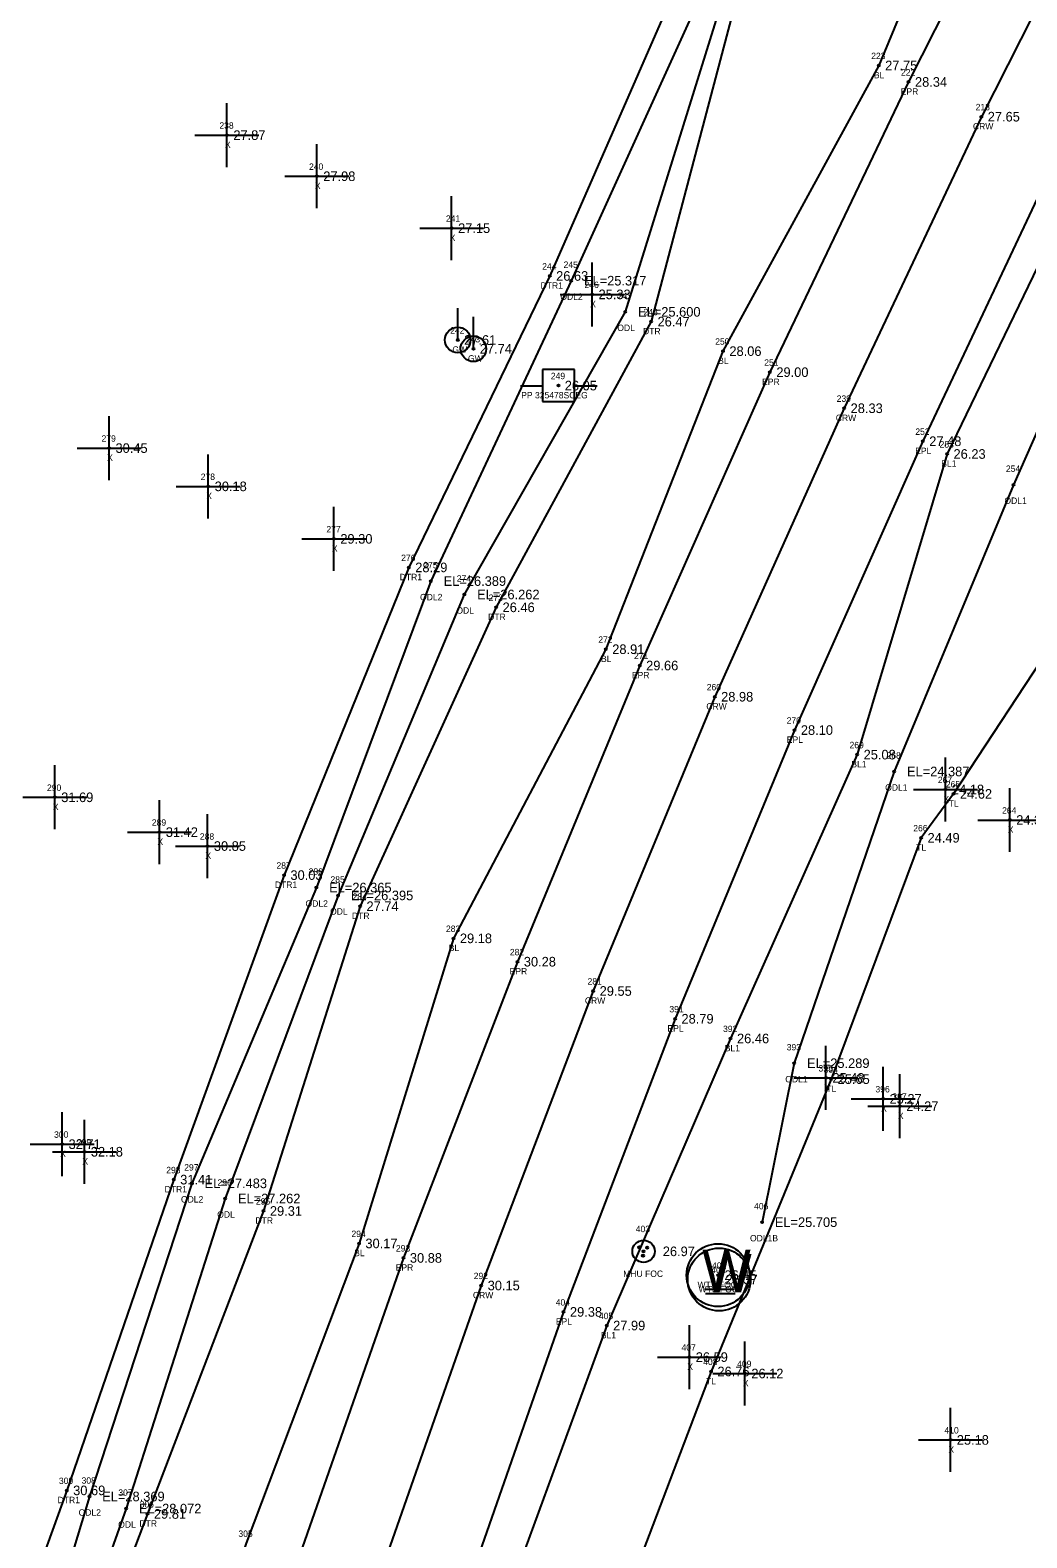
# Model space of a CAD drawing. Extents: x 2042211 to 2045853, y 303080 to 309569.
# Drawn here: x 2042888.3 to 2043044.1, y 307971.4 to 308207.1 of the extents above; entities that cross this region are included whole.
import ezdxf

# ---------------------------------------------------------------- set-up
doc = ezdxf.new("R2010")
doc.units = 0
for name, color, linetype in [('BR_500YR_SCOUR', 7, 'Continuous'), ('RD_DTM_BkLn1', 7, 'Continuous'), ('RD_DTM_BkLn_txCode', 7, 'Continuous'), ('RD_EX_H2O', 7, 'Continuous'), ('RD_EX_H2O_txCode', 7, 'Continuous'), ('RD_EX_Misc', 7, 'Continuous'), ('RD_EX_Misc_txCode', 7, 'Continuous'), ('RD_EX_Road', 7, 'Continuous'), ('RD_EX_Road_txCode', 7, 'Continuous'), ('RD_EX_TX_H2O_ELEV', 7, 'Continuous'), ('RD_EX_TX_Misc_ELEV', 7, 'Continuous'), ('RD_EX_TX_Road_ELEV', 7, 'Continuous'), ('RD_EX_TX_UT_ELEV', 7, 'Continuous'), ('RD_EX_TX_VEG_ELEV', 7, 'Continuous'), ('RD_EX_UT_txCode', 7, 'Continuous'), ('RD_EX_VEG_txCode', 7, 'Continuous'), ('RD_HC_Survey_ELEV', 7, 'Continuous'), ('RD_HC_Survey_txCode', 7, 'Continuous'), ('RD_SMD_Locator', 7, 'Continuous')]:
    doc.layers.add(name, color=color, linetype=linetype)

msp = doc.modelspace()

# ---------------------------------------------------------------- linework, layer by layer
at = {"layer": 'BR_500YR_SCOUR'}
for p, q in [((2042955.12, 308158.64), (2042955.12, 308163.64)), ((2042957.57, 308157.26), (2042957.57, 308162.26)), ((2042973.35, 308154.01), (2042968.35, 308154.01)), ((2042968.35, 308154.01), (2042968.35, 308149.01)), ((2042973.35, 308149.01), (2042973.35, 308154.01)), ((2042964.91, 308151.45), (2042968.38, 308151.45)), ((2042973.27, 308151.45), (2042976.91, 308151.45)), ((2042968.35, 308149.01), (2042973.35, 308149.01)), ((2042993.68, 308010.24), (2042998.31, 308010.24)), ((2042993.84, 308009.56), (2042998.47, 308009.56))]:
    msp.add_line(p, q, dxfattribs=at)
msp.add_lwpolyline([(2043048.7, 308112.2), (2043032.62, 308087.68), (2043027.55, 308080.82), (2043013.5, 308043.09), (2042994.71, 307997.39), (2042983.47, 307967.75), (2042952.97, 307870.73), (2042935.66, 307809.47), (2042918.92, 307737.74), (2042902.79, 307636.4), (2042902.54, 307635.29), (2042891, 307519.21), (2042885.61, 307482.85), (2042881.1, 307379.92), (2042880.44, 307351.7), (2042880.19, 307284.9)], dxfattribs=at)
for centre, radius in [((2042955.12, 308158.64), 2), ((2042955.12, 308158.64), 0.15), ((2042957.57, 308157.26), 2), ((2042957.57, 308157.26), 0.15), ((2042970.85, 308151.51), 0.15), ((2043032.62, 308087.68), 0.15), ((2043027.55, 308080.82), 0.15), ((2043013.5, 308043.09), 0.15), ((2042984.17, 308016.17), 1.75), ((2042983.51, 308016.8), 0.175), ((2042984.17, 308016.17), 0.15), ((2042984.73, 308016.73), 0.175), ((2042995.81, 308012.45), 4.91), ((2042995.97, 308011.76), 4.91), ((2042984.08, 308015.51), 0.175), ((2042995.81, 308012.45), 0.15), ((2042995.97, 308011.76), 0.15), ((2042994.71, 307997.39), 0.15)]:
    msp.add_circle(centre, radius, dxfattribs=at)
at = {"layer": 'RD_DTM_BkLn1'}
for points in [[(2043146.35, 308418.61), (2043116.28, 308377.51), (2043090.22, 308335.44), (2043066.45, 308290.88), (2043040.21, 308248.13), (2043020.93, 308201.56), (2042996.58, 308156.9), (2042978.27, 308110.3), (2042954.46, 308065.1), (2042939.69, 308017.41), (2042922.06, 307970.53), (2042906.59, 307922.57), (2042893.03, 307873.93), (2042879.97, 307825.46), (2042869.74, 307776.07), (2042859.54, 307726.73)], [(2043161.13, 308408.97), (2043133.81, 308366.92), (2043082.92, 308281.6), (2043059.61, 308238.25), (2043036.96, 308193.55), (2043015.53, 308147.97), (2042995.29, 308102.87), (2042976.3, 308056.87), (2042958.8, 308010.83), (2042942.32, 307963.75), (2042927.06, 307916.53), (2042912.57, 307868.35), (2042899.47, 307820.61), (2042887.68, 307772.41), (2042877.12, 307722.98), (2042868.22, 307675.1), (2042860.12, 307626.05), (2042853.34, 307576.87), (2042847.77, 307527.39), (2042843.87, 307477.74), (2042841.31, 307428.69), (2042840.04, 307379.1), (2042839.81, 307329.37), (2042840.93, 307280.46)], [(2043084.04, 308249.78), (2043074.97, 308230.46), (2043053.22, 308185.62), (2043031.61, 308140.82), (2043017.56, 308093.82), (2042997.77, 308049.45), (2042978.41, 308004.57), (2042961.32, 307957.89), (2042945.16, 307911.22), (2042932.79, 307863.05), (2042919.73, 307815.78), (2042908.87, 307767.34), (2042898.28, 307719.5), (2042889.52, 307671.44), (2042882.14, 307623.35), (2042877.76, 307594.41)]]:
    msp.add_lwpolyline(points, dxfattribs=at)
at = {"layer": 'RD_EX_H2O'}
for points in [[(2043129.27, 308428.82), (2043103.11, 308386.53), (2043087.59, 308358.52), (2043078.21, 308342.14), (2043052.09, 308299.16), (2043025.98, 308255.36), (2043015.05, 308240.46), (2043007.57, 308236.11), (2042996.98, 308213.48), (2042981.31, 308163.04), (2042956.15, 308118.86), (2042936.41, 308071.81), (2042918.77, 308024.43), (2042903.29, 307975.96), (2042886.4, 307928.42), (2042872.04, 307879.53), (2042857.18, 307831.23), (2042843.33, 307782.22), (2042831.48, 307730.99), (2042823.97, 307682.68), (2042817.59, 307631.17), (2042809.6, 307580.86), (2042807.78, 307554.78)], [(2043043.85, 308319.04), (2043032.27, 308309.6), (2043013.89, 308261.63), (2043005.61, 308245.64), (2043001.64, 308238.83), (2042990.42, 308216.49), (2042969.5, 308168.65), (2042947.48, 308123.09), (2042927.97, 308074.99), (2042910.74, 308027.38), (2042894.01, 307978.8), (2042876.75, 307931.05), (2042864.86, 307881.34), (2042850.03, 307832.86), (2042838.55, 307782.98)], [(2043049.1, 308319.34), (2043039.24, 308307.44), (2043016.82, 308260.67), (2043010.35, 308243.14), (2043005.62, 308237.14), (2042994.18, 308214.82), (2042972.85, 308167.91), (2042950.92, 308120.95), (2042933.02, 308073.04), (2042913.55, 308026.8), (2042897.55, 307977.85), (2042882.86, 307929.46), (2042868.15, 307880.57), (2042854.72, 307831.84), (2042841.01, 307782.54)], [(2043009.25, 308234.96), (2042998.85, 308212.71), (2042985.35, 308161.51), (2042961.13, 308116.85), (2042939.86, 308070.12), (2042924.76, 308022.48), (2042906.64, 307975.12), (2042888.69, 307927.84), (2042874.66, 307878.9), (2042861.89, 307830.47), (2042846.22, 307781.58)], [(2043061.8, 308180.79), (2043041.98, 308136.02), (2043023.34, 308091.19), (2043007.72, 308045.58), (2043002.68, 308020.73)]]:
    msp.add_lwpolyline(points, dxfattribs=at)
at = {"layer": 'RD_EX_Misc'}
for p, q in [((2042919.05, 308185.67), (2042919.05, 308195.67)), ((2042914.05, 308190.67), (2042924.05, 308190.67)), ((2042933.1, 308179.24), (2042933.1, 308189.24)), ((2042928.1, 308184.24), (2042938.1, 308184.24)), ((2042954.17, 308171.12), (2042954.17, 308181.12)), ((2042949.17, 308176.12), (2042959.17, 308176.12)), ((2042976.13, 308160.77), (2042976.13, 308170.77)), ((2042971.13, 308165.77), (2042981.13, 308165.77)), ((2042900.63, 308136.74), (2042900.63, 308146.74)), ((2042895.63, 308141.74), (2042905.63, 308141.74)), ((2042916.13, 308130.76), (2042916.13, 308140.76)), ((2042911.13, 308135.76), (2042921.13, 308135.76)), ((2042935.77, 308122.55), (2042935.77, 308132.55)), ((2042930.77, 308127.55), (2042940.77, 308127.55)), ((2042892.14, 308082.15), (2042892.14, 308092.15)), ((2043031.37, 308083.37), (2043031.37, 308093.37)), ((2042887.14, 308087.15), (2042897.14, 308087.15)), ((2043026.37, 308088.37), (2043036.37, 308088.37)), ((2043041.41, 308078.6), (2043041.41, 308088.6)), ((2042908.49, 308076.71), (2042908.49, 308086.71)), ((2042916, 308074.53), (2042916, 308084.53)), ((2043036.41, 308083.6), (2043046.41, 308083.6)), ((2042903.49, 308081.71), (2042913.49, 308081.71)), ((2042911, 308079.53), (2042921, 308079.53)), ((2043012.68, 308038.28), (2043012.68, 308048.28)), ((2043021.61, 308035.01), (2043021.61, 308045.01)), ((2043007.68, 308043.28), (2043017.68, 308043.28)), ((2043024.23, 308033.86), (2043024.23, 308043.86)), ((2043016.61, 308040.01), (2043026.61, 308040.01)), ((2042893.29, 308027.92), (2042893.29, 308037.92)), ((2043019.23, 308038.86), (2043029.23, 308038.86)), ((2042896.77, 308026.74), (2042896.77, 308036.74)), ((2042888.29, 308032.92), (2042898.29, 308032.92)), ((2042891.77, 308031.74), (2042901.77, 308031.74)), ((2042991.32, 307994.64), (2042991.32, 308004.64)), ((2043000.01, 307992.07), (2043000.01, 308002.07)), ((2042986.32, 307999.64), (2042996.32, 307999.64)), ((2042995.01, 307997.07), (2043005.01, 307997.07)), ((2043032.12, 307981.69), (2043032.12, 307991.69)), ((2043027.12, 307986.69), (2043037.12, 307986.69))]:
    msp.add_line(p, q, dxfattribs=at)
at = {"layer": 'RD_EX_Road'}
for points in [[(2043150.45, 308415.87), (2043123.31, 308373.62), (2043097.1, 308331.18), (2043072.09, 308287.75), (2043048.26, 308243.82), (2043025.59, 308198.98), (2043003.92, 308153.61), (2042983.57, 308107.75), (2042964.45, 308061.45), (2042946.64, 308015.14), (2042930.05, 307967.71), (2042914.65, 307920.21), (2042900.21, 307872.25), (2042887.2, 307823.91), (2042875.38, 307775.02), (2042864.88, 307726.03)], [(2043172.79, 308402.16), (2043145.1, 308359.37), (2043119.63, 308317.71), (2043094.79, 308274.94), (2043071.92, 308232.51), (2043049.11, 308188.03), (2043027.82, 308142.81), (2043007.75, 308097.66), (2042989.09, 308052.53), (2042971.66, 308006.7), (2042955.42, 307960.12), (2042939.67, 307912.41), (2042925.65, 307865.09), (2042912.69, 307817.39), (2042901.29, 307769.38)]]:
    msp.add_lwpolyline(points, dxfattribs=at)
at = {"layer": 'RD_SMD_Locator'}
for centre in [(2043020.93, 308201.56), (2043025.59, 308198.98), (2043036.96, 308193.55), (2042919.05, 308190.67), (2042933.1, 308184.24), (2042954.17, 308176.12), (2042969.5, 308168.65), (2042972.85, 308167.91), (2042976.13, 308165.77), (2042981.31, 308163.04), (2042985.35, 308161.51), (2042996.58, 308156.9), (2043003.92, 308153.61), (2043015.53, 308147.97), (2042900.63, 308141.74), (2043027.82, 308142.81), (2043031.61, 308140.82), (2042916.13, 308135.76), (2043041.98, 308136.02), (2042935.77, 308127.55), (2042947.48, 308123.09), (2042950.92, 308120.95), (2042956.15, 308118.86), (2042961.13, 308116.85), (2042978.27, 308110.3), (2042983.57, 308107.75), (2042995.29, 308102.87), (2043007.75, 308097.66), (2043017.56, 308093.82), (2043023.34, 308091.19), (2042892.14, 308087.15), (2043031.37, 308088.37), (2043041.41, 308083.6), (2042908.49, 308081.71), (2042916, 308079.53), (2042927.97, 308074.99), (2042933.02, 308073.04), (2042936.41, 308071.81), (2042939.86, 308070.12), (2042954.46, 308065.1), (2042964.45, 308061.45), (2042976.3, 308056.87), (2042989.09, 308052.53), (2042997.77, 308049.45), (2043007.72, 308045.58), (2043012.68, 308043.28), (2043021.61, 308040.01), (2043024.23, 308038.86), (2042893.29, 308032.92), (2042896.77, 308031.74), (2042910.74, 308027.38), (2042913.55, 308026.8), (2042918.77, 308024.43), (2042924.76, 308022.48), (2043002.68, 308020.73), (2042939.69, 308017.41), (2042946.64, 308015.14), (2042958.8, 308010.83), (2042971.66, 308006.7), (2042978.41, 308004.57), (2042991.32, 307999.64), (2043000.01, 307997.07), (2043032.12, 307986.69), (2042894.01, 307978.8), (2042897.55, 307977.85), (2042903.29, 307975.96), (2042906.64, 307975.12)]:
    msp.add_circle(centre, 0.15, dxfattribs=at)

# ---------------------------------------------------------------- texts
at = {"layer": 'BR_500YR_SCOUR'}
for p in [(2042993.35, 308010.45), (2042993.5, 308009.76)]:
    msp.add_text('W', height=6, dxfattribs=at).set_placement(p)
at = {"layer": 'RD_DTM_BkLn_txCode'}
for s, p in [('223', (2043019.75, 308202.56)), ('BL', (2043020.17, 308199.56)), ('250', (2042995.36, 308157.9)), ('BL', (2042995.83, 308154.9)), ('253', (2043030.43, 308141.82)), ('BL1', (2043030.69, 308138.82)), ('272', (2042977.09, 308111.3)), ('BL', (2042977.51, 308108.3)), ('269', (2043016.36, 308094.82)), ('BL1', (2043016.64, 308091.82)), ('283', (2042953.28, 308066.1)), ('BL', (2042953.71, 308063.1)), ('392', (2042996.59, 308050.45)), ('BL1', (2042996.85, 308047.45)), ('294', (2042938.51, 308018.41)), ('BL', (2042938.93, 308015.41)), ('405', (2042977.19, 308005.57)), ('BL1', (2042977.49, 308002.57)), ('305', (2042920.84, 307971.53))]:
    msp.add_text(s, height=1, dxfattribs=at).set_placement(p)
at = {"layer": 'RD_EX_H2O_txCode'}
for s, p in [('244', (2042968.32, 308169.65)), ('245', (2042971.67, 308169.91)), ('DTR1', (2042968.07, 308166.65)), ('ODL2', (2042971.16, 308164.91)), ('247', (2042980.13, 308165.04)), ('248', (2042984.16, 308162.51)), ('ODL', (2042980.06, 308160.04)), ('DTR', (2042984.08, 308159.51)), ('254', (2043040.8, 308138.02)), ('ODL1', (2043040.57, 308133.02)), ('276', (2042946.28, 308124.09)), ('275', (2042949.74, 308122.95)), ('DTR1', (2042946.05, 308121.09)), ('274', (2042954.97, 308120.86)), ('ODL2', (2042949.23, 308117.95)), ('273', (2042959.95, 308117.85)), ('ODL', (2042954.91, 308115.86)), ('DTR', (2042959.87, 308114.85)), ('268', (2043022.14, 308093.19)), ('ODL1', (2043021.93, 308088.19)), ('287', (2042926.79, 308075.99)), ('286', (2042931.82, 308075.04)), ('DTR1', (2042926.54, 308072.99)), ('285', (2042935.23, 308073.81)), ('ODL2', (2042931.33, 308070.04)), ('284', (2042938.68, 308071.12)), ('ODL', (2042935.17, 308068.81)), ('DTR', (2042938.59, 308068.12)), ('393', (2043006.54, 308047.58)), ('ODL1', (2043006.31, 308042.58)), ('298', (2042909.56, 308028.38)), ('297', (2042912.37, 308028.8)), ('DTR1', (2042909.31, 308025.38)), ('296', (2042917.57, 308026.43)), ('ODL2', (2042911.86, 308023.8)), ('295', (2042923.58, 308023.48)), ('406', (2043001.44, 308022.73)), ('ODL', (2042917.53, 308021.43)), ('DTR', (2042923.5, 308020.48)), ('ODL1B', (2043000.8, 308017.73)), ('308', (2042896.33, 307979.85)), ('309', (2042892.79, 307979.8)), ('307', (2042902.07, 307977.96)), ('DTR1', (2042892.58, 307976.8)), ('306', (2042905.4, 307976.12)), ('ODL2', (2042895.86, 307974.85)), ('ODL', (2042902.05, 307972.96)), ('DTR', (2042905.37, 307973.12))]:
    msp.add_text(s, height=1, dxfattribs=at).set_placement(p)
at = {"layer": 'RD_EX_Misc_txCode'}
for s, p in [('238', (2042917.87, 308191.67)), ('X', (2042918.74, 308188.67)), ('240', (2042931.88, 308185.24)), ('X', (2042932.79, 308182.24)), ('241', (2042953.27, 308177.12)), ('X', (2042953.86, 308174.12)), ('246', (2042974.93, 308166.77)), ('X', (2042975.82, 308163.77)), ('279', (2042899.45, 308142.74)), ('X', (2042900.32, 308139.74)), ('278', (2042914.95, 308136.76)), ('X', (2042915.81, 308133.76)), ('277', (2042934.59, 308128.55)), ('X', (2042935.45, 308125.55)), ('267', (2043030.16, 308089.37)), ('290', (2042890.92, 308088.15)), ('X', (2043031.05, 308086.37)), ('X', (2042891.83, 308085.15)), ('264', (2043040.2, 308084.6)), ('289', (2042907.31, 308082.71)), ('X', (2043041.09, 308081.6)), ('X', (2042908.18, 308079.71)), ('288', (2042914.82, 308080.53)), ('X', (2042915.68, 308077.53)), ('395', (2043011.5, 308044.28)), ('X', (2043012.37, 308041.28)), ('396', (2043020.41, 308041.01)), ('397', (2043023.05, 308039.86)), ('X', (2043021.29, 308038.01)), ('X', (2043023.92, 308036.86)), ('300', (2042892.03, 308033.92)), ('299', (2042895.59, 308032.74)), ('X', (2042892.98, 308030.92)), ('X', (2042896.45, 308029.74)), ('407', (2042990.1, 308000.64)), ('X', (2042991, 307997.64)), ('409', (2042998.79, 307998.07)), ('X', (2042999.69, 307995.07)), ('410', (2043031.19, 307987.69)), ('X', (2043031.81, 307984.69))]:
    msp.add_text(s, height=1, dxfattribs=at).set_placement(p)
at = {"layer": 'RD_EX_Road_txCode'}
for s, p in [('222', (2043024.41, 308199.98)), ('EPR', (2043024.36, 308196.98)), ('251', (2043003.02, 308154.61)), ('EPR', (2043002.69, 308151.61)), ('252', (2043026.64, 308143.81)), ('EPL', (2043026.62, 308140.81)), ('271', (2042982.67, 308108.75)), ('EPR', (2042982.34, 308105.75)), ('270', (2043006.53, 308098.66)), ('EPL', (2043006.55, 308095.66)), ('282', (2042963.27, 308062.45)), ('EPR', (2042963.23, 308059.45)), ('391', (2042988.2, 308053.53)), ('EPL', (2042987.89, 308050.53)), ('293', (2042945.46, 308016.14)), ('EPR', (2042945.42, 308013.14)), ('404', (2042970.44, 308007.7)), ('EPL', (2042970.45, 308004.7))]:
    msp.add_text(s, height=1, dxfattribs=at).set_placement(p)
at = {"layer": 'RD_EX_TX_H2O_ELEV'}
for s, p in [('26.63', (2042970.5, 308167.9)), ('EL=25.317', (2042974.85, 308167.16)), ('EL=25.600', (2042983.31, 308162.29)), ('26.47', (2042986.35, 308160.76)), ('28.29', (2042948.48, 308122.34)), ('EL=26.389', (2042952.92, 308120.2)), ('EL=26.262', (2042958.15, 308118.11)), ('26.46', (2042962.13, 308116.1)), ('EL=24.387', (2043025.34, 308090.44)), ('30.03', (2042928.97, 308074.24)), ('EL=26.365', (2042935.02, 308072.29)), ('EL=26.395', (2042938.41, 308071.06)), ('27.74', (2042940.86, 308069.37)), ('EL=25.289', (2043009.72, 308044.83)), ('31.41', (2042911.74, 308026.63)), ('EL=27.483', (2042915.55, 308026.05)), ('EL=27.262', (2042920.77, 308023.68)), ('29.31', (2042925.76, 308021.73)), ('EL=25.705', (2043004.68, 308019.98)), ('30.69', (2042895.01, 307978.05)), ('EL=28.369', (2042899.55, 307977.1)), ('EL=28.072', (2042905.29, 307975.21)), ('29.81', (2042907.64, 307974.37))]:
    msp.add_text(s, height=1.5, dxfattribs=at).set_placement(p)
at = {"layer": 'RD_EX_TX_Misc_ELEV'}
for s, p in [('27.75', (2043021.93, 308200.81)), ('27.87', (2042920.05, 308189.92)), ('27.98', (2042934.1, 308183.49)), ('27.15', (2042955.17, 308175.37)), ('25.33', (2042977.13, 308165.02)), ('28.06', (2042997.58, 308156.15)), ('30.45', (2042901.63, 308140.99)), ('26.23', (2043032.61, 308140.07)), ('30.18', (2042917.13, 308135.01)), ('29.30', (2042936.77, 308126.8)), ('28.91', (2042979.27, 308109.55)), ('25.08', (2043018.56, 308093.07)), ('31.69', (2042893.14, 308086.4)), ('24.18', (2043032.37, 308087.62)), ('31.42', (2042909.49, 308080.96)), ('24.38', (2043042.41, 308082.85)), ('30.85', (2042917, 308078.78)), ('29.18', (2042955.46, 308064.35)), ('26.46', (2042998.77, 308048.7)), ('25.48', (2043013.68, 308042.53)), ('25.27', (2043022.61, 308039.26)), ('24.27', (2043025.23, 308038.11)), ('32.71', (2042894.29, 308032.17)), ('32.18', (2042897.77, 308030.99)), ('30.17', (2042940.69, 308016.66)), ('27.99', (2042979.41, 308003.82)), ('26.59', (2042992.32, 307998.89)), ('26.12', (2043001.01, 307996.32)), ('25.18', (2043033.12, 307985.94))]:
    msp.add_text(s, height=1.5, dxfattribs=at).set_placement(p)
at = {"layer": 'RD_EX_TX_Road_ELEV'}
for s, p in [('28.34', (2043026.59, 308198.23)), ('29.00', (2043004.92, 308152.86)), ('27.48', (2043028.82, 308142.06)), ('29.66', (2042984.57, 308107)), ('28.10', (2043008.75, 308096.91)), ('30.28', (2042965.45, 308060.7)), ('28.79', (2042990.09, 308051.78)), ('30.88', (2042947.64, 308014.39)), ('29.38', (2042972.66, 308005.95))]:
    msp.add_text(s, height=1.5, dxfattribs=at).set_placement(p)
at = {"layer": 'RD_EX_TX_UT_ELEV'}
for s, p in [('27.61', (2042956.12, 308157.89)), ('27.74', (2042958.57, 308156.51)), ('26.97', (2042987.17, 308015.42)), ('26.45', (2042996.81, 308011.7)), ('26.37', (2042996.97, 308011.01))]:
    msp.add_text(s, height=1.5, dxfattribs=at).set_placement(p)
at = {"layer": 'RD_EX_TX_VEG_ELEV'}
for s, p in [('24.62', (2043033.62, 308086.93)), ('24.49', (2043028.55, 308080.07)), ('25.65', (2043014.5, 308042.34)), ('26.76', (2042995.71, 307996.64))]:
    msp.add_text(s, height=1.5, dxfattribs=at).set_placement(p)
at = {"layer": 'RD_EX_UT_txCode'}
for s, p in [('242', (2042953.94, 308159.64)), ('GW', (2042954.28, 308156.64)), ('243', (2042956.38, 308158.26)), ('GW', (2042956.72, 308155.26)), ('249', (2042969.67, 308152.51)), ('PP 325478SCEG', (2042965.04, 308149.51)), ('403', (2042982.95, 308019.17)), ('401', (2042994.87, 308013.45)), ('MHU FOC', (2042980.98, 308012.17)), ('402', (2042994.75, 308012.76)), ('WTS FOC', (2042992.6, 308010.45)), ('WTS FOC', (2042992.76, 308009.76))]:
    msp.add_text(s, height=1, dxfattribs=at).set_placement(p)
at = {"layer": 'RD_EX_VEG_txCode'}
for s, p in [('265', (2043031.42, 308088.68)), ('TL', (2043031.85, 308085.68)), ('266', (2043026.32, 308081.82)), ('TL', (2043026.78, 308078.82)), ('394', (2043012.32, 308044.09)), ('TL', (2043012.73, 308041.09)), ('408', (2042993.49, 307998.39)), ('TL', (2042993.94, 307995.39))]:
    msp.add_text(s, height=1, dxfattribs=at).set_placement(p)
at = {"layer": 'RD_HC_Survey_ELEV'}
for s, p in [('27.65', (2043037.96, 308192.8)), ('26.05', (2042971.85, 308150.76)), ('28.33', (2043016.53, 308147.22)), ('28.98', (2042996.29, 308102.12)), ('29.55', (2042977.3, 308056.12)), ('30.15', (2042959.8, 308010.08))]:
    msp.add_text(s, height=1.5, dxfattribs=at).set_placement(p)
at = {"layer": 'RD_HC_Survey_txCode'}
for s, p in [('213', (2043036.07, 308194.55)), ('CRW', (2043035.65, 308191.55)), ('239', (2043014.35, 308148.97)), ('CRW', (2043014.21, 308145.97)), ('260', (2042994.04, 308103.87)), ('CRW', (2042993.97, 308100.87)), ('281', (2042975.41, 308057.87)), ('CRW', (2042974.99, 308054.87)), ('292', (2042957.62, 308011.83)), ('CRW', (2042957.49, 308008.83))]:
    msp.add_text(s, height=1, dxfattribs=at).set_placement(p)

doc.saveas('drawing.dxf')
